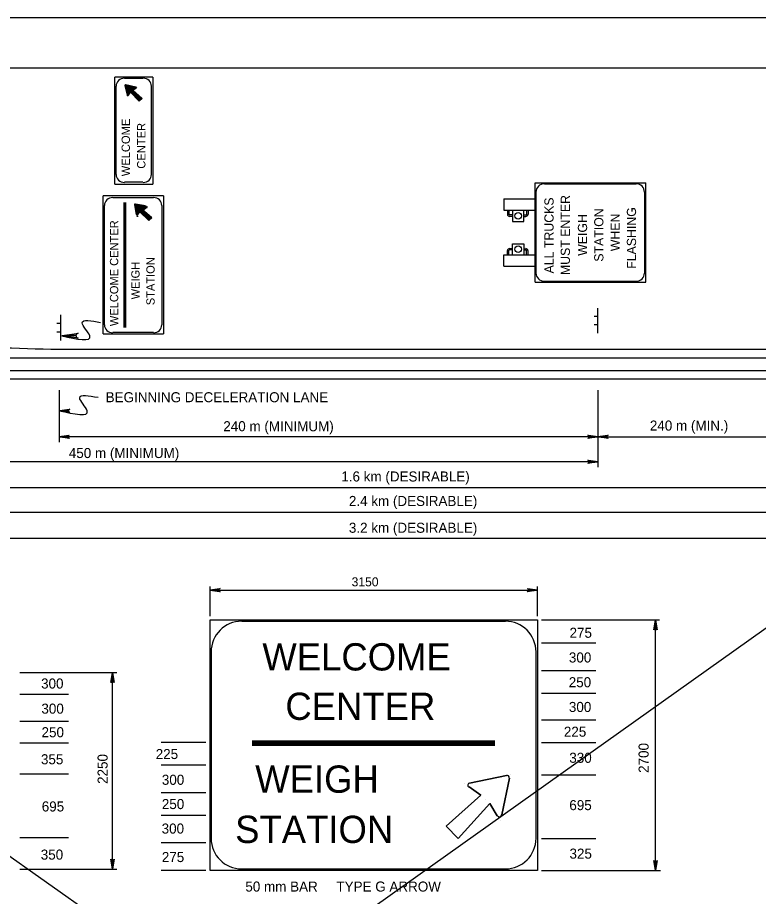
# Model space of a CAD drawing. Extents: x 2189973 to 2192941, y 2147557 to 2151454.
# Drawn here: x 2191146 to 2191872, y 2150594 to 2151454 of the extents above; entities that cross this region are included whole.
import ezdxf

# ---------------------------------------------------------------- set-up
doc = ezdxf.new("R2010")
doc.units = 0
for name, color, linetype in [('1', 7, 'Continuous'), ('Default', 7, 'Continuous'), ('PLT-BNDY', 7, 'Continuous')]:
    doc.layers.add(name, color=color, linetype=linetype)

# ---------------------------------------------------------------- blocks, each defined once
blk = doc.blocks.new('RARROW')
at = {"layer": 'Default'}
blk.add_lwpolyline([(-18.156, 2.28), (-17.479, 0.966), (0, 0), (-18.156, 2.28), (-19.086, 3.077), (0, 0), (-17.465, -0.864), (-18.103, -2.164), (0, 0), (-19.086, -3.033), (-18.103, -2.164)], dxfattribs=at)

msp = doc.modelspace()

# ---------------------------------------------------------------- linework, layer by layer
at = {"layer": '1'}
for p, q in [((2192688.33, 2151431.03), (2190039.06, 2149549.03)), ((2190017.34, 2151423.79), (2192695.57, 2149534.55))]:
    msp.add_line(p, q, dxfattribs=at)
at = {"layer": 'Default'}
for p, q in [((2190104.48, 2151405.2), (2192683.21, 2151405.2)), ((2191241.29, 2151291.19), (2191241.29, 2151396.18)), ((2191278.61, 2151396.18), (2191241.29, 2151396.18)), ((2191250.72, 2151394.94), (2191268.77, 2151394.94)), ((2191278.61, 2151396.18), (2191278.61, 2151291.19)), ((2191242.52, 2151300.62), (2191242.52, 2151387.15)), ((2191251.13, 2151388.38), (2191251.13, 2151388.38)), ((2191251.13, 2151387.56), (2191253.18, 2151378.54)), ((2191261.79, 2151386.33), (2191251.95, 2151388.38)), ((2191257.69, 2151382.23), (2191257.69, 2151382.23)), ((2191258.92, 2151383.46), (2191262.2, 2151385.51)), ((2191258.92, 2151383.46), (2191262.2, 2151385.51)), ((2191258.92, 2151383.46), (2191258.92, 2151383.46)), ((2191267.95, 2151375.26), (2191258.92, 2151383.46)), ((2191263.43, 2151386.33), (2191263.43, 2151386.33)), ((2191276.97, 2151387.15), (2191276.97, 2151300.62)), ((2191253.59, 2151376.9), (2191253.59, 2151376.9)), ((2191254.41, 2151378.13), (2191256.46, 2151381.41)), ((2191256.46, 2151381.41), (2191256.46, 2151381.41)), ((2191256.46, 2151381.41), (2191265.07, 2151372.39)), ((2191265.07, 2151372.39), (2191267.95, 2151375.26)), ((2191267.95, 2151375.26), (2191267.95, 2151375.26)), ((2191265.07, 2151372.39), (2191265.07, 2151372.39)), ((2191241.29, 2151291.19), (2191278.61, 2151291.19)), ((2191268.77, 2151293.24), (2191250.72, 2151293.24)), ((2191653.03, 2151195.22), (2191653.03, 2151292.42)), ((2191653.03, 2151292.42), (2191761.3, 2151292.42)), ((2191662.06, 2151291.6), (2191751.87, 2151291.6)), ((2191761.3, 2151195.22), (2191761.3, 2151292.42)), ((2191229.81, 2151144.78), (2191229.81, 2151279.71)), ((2191288.86, 2151279.71), (2191229.81, 2151279.71)), ((2191288.86, 2151279.71), (2191288.86, 2151144.78)), ((2191653.85, 2151204.25), (2191653.85, 2151283.4)), ((2191760.07, 2151283.4), (2191760.07, 2151204.25)), ((2191231.04, 2151153.39), (2191231.04, 2151270.27)), ((2191239.24, 2151278.07), (2191279.02, 2151278.07)), ((2191250.31, 2151150.93), (2191250.31, 2151273.14)), ((2191250.72, 2151150.93), (2191250.72, 2151273.14)), ((2191251.13, 2151150.93), (2191251.13, 2151273.14)), ((2191251.54, 2151150.93), (2191251.54, 2151273.14)), ((2191251.95, 2151150.93), (2191251.95, 2151273.14)), ((2191260.15, 2151271.91), (2191260.15, 2151271.91)), ((2191260.56, 2151271.09), (2191262.61, 2151261.66)), ((2191271.23, 2151269.86), (2191261.38, 2151271.5)), ((2191287.22, 2151270.27), (2191287.22, 2151153.39)), ((2191622.28, 2151276.83), (2191622.28, 2151265.76)), ((2191622.28, 2151276.83), (2191653.03, 2151276.83)), ((2191263.43, 2151261.25), (2191265.89, 2151264.12)), ((2191265.89, 2151264.12), (2191265.89, 2151264.12)), ((2191265.89, 2151264.12), (2191274.51, 2151255.51)), ((2191266.31, 2151263.3), (2191266.31, 2151263.3)), ((2191266.72, 2151265.35), (2191266.72, 2151265.35)), ((2191267.54, 2151264.53), (2191267.54, 2151264.53)), ((2191267.95, 2151266.58), (2191271.64, 2151268.63)), ((2191267.95, 2151266.58), (2191271.64, 2151268.63)), ((2191267.95, 2151266.58), (2191267.95, 2151266.58)), ((2191277.38, 2151258.38), (2191267.95, 2151266.58)), ((2191268.77, 2151265.76), (2191272.46, 2151268.63)), ((2191268.77, 2151265.76), (2191268.77, 2151265.76)), ((2191272.87, 2151269.45), (2191272.87, 2151269.45)), ((2191622.28, 2151265.76), (2191630.89, 2151265.76)), ((2191625.97, 2151265.76), (2191625.97, 2151261.66)), ((2191627.2, 2151265.76), (2191627.2, 2151261.66)), ((2191630.89, 2151265.76), (2191630.89, 2151254.69)), ((2191630.89, 2151265.76), (2191653.03, 2151265.76)), ((2191641.96, 2151254.69), (2191641.96, 2151265.76)), ((2191644.42, 2151265.76), (2191644.42, 2151261.66)), ((2191646.06, 2151265.76), (2191646.06, 2151261.66)), ((2191263.02, 2151260.02), (2191263.02, 2151260.02)), ((2191274.51, 2151255.51), (2191277.38, 2151258.38)), ((2191274.51, 2151255.51), (2191274.51, 2151255.51)), ((2191277.38, 2151258.38), (2191277.38, 2151258.38)), ((2191630.89, 2151261.25), (2191628.02, 2151261.25)), ((2191630.89, 2151259.61), (2191628.02, 2151259.61)), ((2191630.89, 2151254.69), (2191641.96, 2151254.69)), ((2191641.96, 2151261.25), (2191643.6, 2151261.25)), ((2191641.96, 2151259.61), (2191643.6, 2151259.61)), ((2191630.89, 2151228.03), (2191628.02, 2151228.03)), ((2191630.89, 2151221.88), (2191630.89, 2151232.95)), ((2191630.89, 2151232.95), (2191641.96, 2151232.95)), ((2191641.96, 2151232.95), (2191641.96, 2151221.88)), ((2191641.96, 2151228.03), (2191643.6, 2151228.03)), ((2191622.28, 2151210.81), (2191622.28, 2151221.88)), ((2191622.28, 2151221.88), (2191630.89, 2151221.88)), ((2191625.97, 2151221.88), (2191625.97, 2151226.39)), ((2191627.2, 2151221.88), (2191627.2, 2151226.39)), ((2191630.89, 2151226.8), (2191628.02, 2151226.8)), ((2191630.89, 2151221.88), (2191653.03, 2151221.88)), ((2191641.96, 2151226.8), (2191643.6, 2151226.8)), ((2191644.42, 2151221.88), (2191644.42, 2151226.39)), ((2191646.06, 2151221.88), (2191646.06, 2151226.39)), ((2191622.28, 2151210.81), (2191653.03, 2151210.81)), ((2191653.03, 2151195.22), (2191761.3, 2151195.22)), ((2191751.87, 2151196.04), (2191662.06, 2151196.04)), ((2191714.55, 2151145.19), (2191714.55, 2151169.8)), ((2191188.39, 2151138.22), (2191188.39, 2151163.24)), ((2191714.55, 2151161.6), (2191710.86, 2151161.6)), ((2191188.39, 2151154.62), (2191184.28, 2151154.62)), ((2191714.55, 2151153.39), (2191710.86, 2151153.39)), ((2191188.39, 2151146.42), (2191184.28, 2151146.42)), ((2191229.81, 2151144.78), (2191288.86, 2151144.78)), ((2191279.02, 2151146.01), (2191239.24, 2151146.01)), ((2191186.33, 2151129.61), (2191186.33, 2151129.61)), ((2191186.33, 2151129.61), (2192679.93, 2151129.61)), ((2190114.32, 2151121), (2192679.93, 2151121)), ((2190114.32, 2151108.69), (2192679.93, 2151108.69)), ((2190114.32, 2151100.49), (2192679.93, 2151100.49)), ((2191186.74, 2151089.42), (2191186.74, 2151038.56)), ((2191714.55, 2151089.42), (2191714.55, 2151013.96)), ((2191714.55, 2151043.9), (2191186.74, 2151043.9)), ((2191714.55, 2151043.9), (2191916.68, 2151043.9)), ((2191714.55, 2151019.29), (2190939.04, 2151019.29)), ((2190939.04, 2150994.27), (2192091.43, 2150994.27)), ((2192264.5, 2150969.67), (2190939.04, 2150969.67)), ((2192437.97, 2150944.24), (2190939.04, 2150944.24)), ((2191334.51, 2150868.2), (2191334.51, 2150897.32)), ((2191334.51, 2150893.63), (2191655.21, 2150893.63)), ((2191655.21, 2150868.2), (2191655.21, 2150897.32)), ((2191334.51, 2150864.51), (2191655.21, 2150864.51)), ((2191334.51, 2150618.86), (2191334.51, 2150864.51)), ((2191624.04, 2150862.87), (2191365.68, 2150862.87)), ((2191655.21, 2150864.51), (2191655.21, 2150618.86)), ((2191659.31, 2150864.51), (2191692.12, 2150864.51)), ((2191659.31, 2150864.51), (2191692.12, 2150864.51)), ((2191681.46, 2150864.51), (2191774.97, 2150864.51)), ((2191770.86, 2150618.86), (2191770.86, 2150864.51)), ((2191659.31, 2150841.96), (2191712.43, 2150841.96)), ((2191335.74, 2150832.93), (2191335.74, 2150650.44)), ((2191653.98, 2150650.44), (2191653.98, 2150832.93)), ((2191659.31, 2150814.89), (2191712.43, 2150814.89)), ((2191148.24, 2150812.94), (2191243.22, 2150812.94)), ((2191239.11, 2150620.19), (2191239.11, 2150812.94)), ((2191148.24, 2150791.62), (2191195.99, 2150791.62)), ((2191659.31, 2150792.74), (2191712.43, 2150792.74)), ((2191148.24, 2150765.37), (2191195.99, 2150765.37)), ((2191659.31, 2150766.5), (2191712.43, 2150766.5)), ((2191375.93, 2150745.99), (2191613.38, 2150745.99)), ((2191375.93, 2150745.17), (2191613.38, 2150745.17)), ((2191148.24, 2150744.04), (2191195.99, 2150744.04)), ((2191330.41, 2150744.35), (2191286.76, 2150744.35)), ((2191375.93, 2150744.35), (2191613.38, 2150744.35)), ((2191375.93, 2150743.53), (2191613.38, 2150743.53)), ((2191375.93, 2150742.71), (2191613.38, 2150742.71)), ((2191375.93, 2150741.89), (2191613.38, 2150741.89)), ((2191659.31, 2150744.35), (2191712.43, 2150744.35)), ((2191330.41, 2150722.21), (2191286.76, 2150722.21)), ((2191148.24, 2150713.7), (2191195.99, 2150713.7)), ((2191624.86, 2150711.95), (2191588.77, 2150704.57)), ((2191588.77, 2150704.57), (2191624.86, 2150711.95)), ((2191628.56, 2150712.77), (2191628.56, 2150712.77)), ((2191659.31, 2150712.77), (2191712.43, 2150712.77)), ((2191583.44, 2150703.75), (2191583.44, 2150703.75)), ((2191620.35, 2150673.4), (2191627.73, 2150709.49)), ((2191627.73, 2150709.49), (2191620.35, 2150673.4)), ((2191330.41, 2150695.14), (2191286.76, 2150695.14)), ((2191588.36, 2150700.88), (2191599.85, 2150692.68)), ((2191599.85, 2150692.68), (2191588.36, 2150700.88)), ((2191599.85, 2150692.68), (2191565.81, 2150662.33)), ((2191565.81, 2150662.33), (2191599.85, 2150692.68)), ((2191599.85, 2150692.68), (2191565.81, 2150662.33)), ((2191565.81, 2150662.33), (2191599.85, 2150692.68)), ((2191599.85, 2150692.68), (2191599.85, 2150692.68)), ((2191599.85, 2150692.68), (2191599.85, 2150692.68)), ((2191603.95, 2150688.99), (2191603.95, 2150688.99)), ((2191603.95, 2150688.99), (2191603.95, 2150688.99)), ((2191577.7, 2150650.44), (2191608.46, 2150684.48)), ((2191608.46, 2150684.48), (2191577.7, 2150650.44)), ((2191608.46, 2150684.48), (2191608.46, 2150684.48)), ((2191608.46, 2150684.48), (2191608.46, 2150684.48)), ((2191608.46, 2150684.48), (2191615.84, 2150672.58)), ((2191615.84, 2150672.58), (2191608.46, 2150684.48)), ((2191330.41, 2150672.99), (2191286.76, 2150672.99)), ((2191618.71, 2150668.07), (2191618.71, 2150668.07)), ((2191565.81, 2150662.33), (2191565.81, 2150662.33)), ((2191565.81, 2150662.33), (2191565.81, 2150662.33)), ((2191565.81, 2150662.33), (2191577.7, 2150650.44)), ((2191577.7, 2150650.44), (2191565.81, 2150662.33)), ((2191148.24, 2150651.36), (2191195.99, 2150651.36)), ((2191330.41, 2150645.93), (2191286.76, 2150645.93)), ((2191577.7, 2150650.44), (2191577.7, 2150650.44)), ((2191577.7, 2150650.44), (2191577.7, 2150650.44)), ((2191659.31, 2150650.44), (2191712.43, 2150650.44)), ((2191148.24, 2150620.19), (2191243.22, 2150620.19)), ((2191330.41, 2150618.86), (2191286.76, 2150618.86)), ((2191655.21, 2150618.86), (2191334.51, 2150618.86)), ((2191365.68, 2150620.5), (2191624.04, 2150620.5)), ((2191659.31, 2150618.86), (2191775.88, 2150618.86))]:
    msp.add_line(p, q, dxfattribs=at)
for points in [[(2191267.54, 2151375.26), (2191265.07, 2151372.8), (2191256.46, 2151381.82), (2191254.41, 2151378.54), (2191254, 2151378.54), (2191253.59, 2151378.54), (2191251.54, 2151387.56), (2191251.95, 2151387.97), (2191262.2, 2151385.92), (2191258.51, 2151383.46), (2191267.54, 2151375.26), (2191265.07, 2151373.21), (2191256.46, 2151381.82), (2191254, 2151378.95), (2191254, 2151378.54), (2191251.95, 2151387.56), (2191261.79, 2151385.92), (2191258.51, 2151383.46), (2191267.13, 2151375.26), (2191265.48, 2151373.62), (2191256.46, 2151382.23), (2191254, 2151379.36), (2191252.36, 2151387.15), (2191260.97, 2151385.51), (2191257.69, 2151383.46), (2191266.72, 2151375.26), (2191265.48, 2151374.03), (2191256.46, 2151382.23), (2191254.41, 2151379.77), (2191252.77, 2151386.74), (2191260.15, 2151385.51), (2191257.69, 2151383.46), (2191266.31, 2151375.26), (2191265.48, 2151374.44), (2191256.46, 2151382.64), (2191254.82, 2151380.59), (2191253.59, 2151386.33), (2191259.74, 2151385.1), (2191256.87, 2151383.46), (2191265.89, 2151375.26), (2191265.48, 2151375.26), (2191256.46, 2151383.05), (2191254.82, 2151381.41), (2191254, 2151385.92), (2191258.92, 2151385.1), (2191256.87, 2151383.46), (2191265.89, 2151375.67), (2191265.48, 2151375.26), (2191265.48, 2151374.85), (2191256.46, 2151383.46), (2191265.48, 2151375.67), (2191265.07, 2151375.26), (2191256.46, 2151383.46), (2191255.23, 2151382.23), (2191254.41, 2151385.51), (2191258.1, 2151384.69), (2191255.64, 2151383.05), (2191254.82, 2151385.1), (2191257.69, 2151384.69), (2191256.05, 2151383.46), (2191255.64, 2151385.1), (2191256.87, 2151384.69), (2191256.05, 2151384.28), (2191256.05, 2151384.69), (2191256.46, 2151384.69)], [(2191276.97, 2151258.79), (2191274.51, 2151256.33), (2191265.89, 2151264.53), (2191263.43, 2151261.66), (2191263.02, 2151261.25), (2191262.61, 2151261.66), (2191260.97, 2151271.09), (2191261.38, 2151271.5), (2191271.64, 2151269.04), (2191267.54, 2151266.58), (2191276.97, 2151258.79), (2191274.51, 2151256.74), (2191265.89, 2151264.94), (2191263.43, 2151261.66), (2191263.43, 2151261.66), (2191261.38, 2151271.09), (2191270.82, 2151269.04), (2191267.54, 2151266.17), (2191276.56, 2151258.79), (2191274.51, 2151257.15), (2191265.89, 2151265.35), (2191263.43, 2151262.07), (2191261.79, 2151270.68), (2191270.41, 2151269.04), (2191266.72, 2151266.17), (2191276.15, 2151258.79), (2191274.92, 2151257.56), (2191265.89, 2151265.35), (2191263.84, 2151262.89), (2191262.2, 2151270.27), (2191269.18, 2151268.63), (2191266.72, 2151266.17), (2191275.74, 2151258.79), (2191274.92, 2151257.97), (2191265.89, 2151265.76), (2191264.25, 2151263.71), (2191262.61, 2151269.86), (2191268.36, 2151268.63), (2191266.31, 2151266.17), (2191275.33, 2151258.79), (2191274.92, 2151258.38), (2191265.89, 2151266.17), (2191264.25, 2151264.53), (2191263.43, 2151269.45), (2191267.95, 2151268.63), (2191265.89, 2151266.17), (2191274.92, 2151258.79), (2191274.92, 2151258.38), (2191274.92, 2151258.38), (2191265.89, 2151266.17), (2191274.92, 2151258.79), (2191274.51, 2151258.38), (2191265.89, 2151266.17), (2191264.66, 2151264.94), (2191263.84, 2151269.04), (2191267.13, 2151268.22), (2191265.07, 2151265.76), (2191264.25, 2151268.63), (2191266.72, 2151268.22), (2191265.07, 2151266.58), (2191264.66, 2151268.22), (2191265.89, 2151268.22), (2191265.48, 2151267.4), (2191265.07, 2151268.22), (2191265.89, 2151267.81)], [(2191203.97, 2151141.09), (2191203.56, 2151142.32), (2191189.21, 2151142.73), (2191203.97, 2151141.09), (2191205.2, 2151140.27), (2191189.21, 2151142.73), (2191203.56, 2151143.55), (2191203.97, 2151144.78), (2191189.21, 2151142.73), (2191205.2, 2151145.19), (2191203.97, 2151144.78)]]:
    msp.add_lwpolyline(points, dxfattribs=at)
for centre in [(2191636.41, 2151260.27), (2191636.41, 2151227.49)]:
    msp.add_circle(centre, 3.21, dxfattribs=at)
for centre, radius, start, end in [((2191661.91, 2151283.55), 8.12, 90, 180), ((2191751.98, 2151283.55), 8.12, 0, 90), ((2191627.91, 2151261.64), 2.01, 180, 270), ((2191627.91, 2151261.64), 0.731, 180, 270), ((2191643.89, 2151261.64), 0.731, 270, 0), ((2191643.89, 2151261.64), 2.01, 270, 0), ((2191627.91, 2151226.12), 2.01, 90, 180), ((2191643.89, 2151226.12), 2.01, 0, 90), ((2191627.91, 2151226.12), 0.731, 90, 180), ((2191643.89, 2151226.12), 0.731, 0, 90), ((2191661.91, 2151204.21), 8.12, 180, 270), ((2191751.98, 2151204.21), 8.12, 270, 0), ((2191297.63, 2155830.32), 4702.16, 265.6447, 268.64351), ((2191365.55, 2150833.13), 30, 90, 180), ((2191623.86, 2150833.13), 30, 0, 90), ((2191625.41, 2150709.98), 2.25, 348.26016, 101.73982), ((2191625.41, 2150709.98), 2.25, 348.26016, 101.73982), ((2191589.27, 2150702.47), 2.25, 101.73984, 236.68377), ((2191589.27, 2150702.47), 2.25, 101.73984, 236.68377), ((2191617.9, 2150673.84), 2.25, 213.31623, 348.26016), ((2191617.9, 2150673.84), 2.25, 213.31623, 348.26016), ((2191365.55, 2150650.53), 30, 180, 270), ((2191623.86, 2150650.53), 30, 270, 0)]:
    msp.add_arc(centre, radius, start, end, dxfattribs=at)
for centre, major_axis, start_param, end_param in [((2191250.71, 2151387.26), (-8.16, 0), 4.712389, 6.283185), ((2191269.02, 2151387.26), (8.16, 0), 0, 1.570796), ((2191251.81, 2151387.91), (-0.619, 0), 4.50749, 6.488084), ((2191261.75, 2151385.95), (0.619, 0), 5.293867, 7.649083), ((2191253.87, 2151378.47), (0.619, 0), 3.346491, 5.701707), ((2191250.71, 2151300.64), (-8.16, 0), 0, 1.570796), ((2191269.02, 2151300.64), (8.16, 0), 4.712389, 6.283185), ((2191239.23, 2151270.39), (-8.12, 0), 4.712389, 6.283185), ((2191261.07, 2151271.04), (-0.619, 0), 4.50749, 6.488084), ((2191261.15, 2151270.96), (-0.688, 0), 4.50749, 6.488084), ((2191279.18, 2151270.39), (8.12, 0), 0, 1.570796), ((2191271.01, 2151269.07), (0.619, 0), 5.293867, 7.649083), ((2191272.19, 2151268.78), (0.688, 0), 5.293867, 7.649083), ((2191263.14, 2151261.59), (0.619, 0), 3.346491, 5.701707), ((2191263.44, 2151260.47), (0.688, 0), 3.346491, 5.701707), ((2191239.23, 2151153.46), (-8.12, 0), 0, 1.570796), ((2191279.18, 2151153.46), (8.12, 0), 4.712389, 6.283185)]:
    msp.add_ellipse(centre, major_axis=major_axis, ratio=0.95, start_param=start_param, end_param=end_param, dxfattribs=at)
for points in [[(2191189.21, 2151142.73), (2191216.68, 2151142.73), (2191209.3, 2151155.44), (2191227.35, 2151155.85)], [(2191186.74, 2151069.32), (2191214.22, 2151069.32), (2191206.84, 2151082.04), (2191224.88, 2151082.45)]]:
    msp.add_spline(points, degree=3, dxfattribs=at)
at = {"layer": 'PLT-BNDY'}
msp.add_lwpolyline([(2189973.25, 2151454.41), (2192732.43, 2151454.41), (2192732.43, 2149505.6), (2189973.25, 2149505.6)], close=True, dxfattribs=at)

# ---------------------------------------------------------------- block references
at = {"layer": 'Default', "xscale": 0.515679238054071, "yscale": 0.5369477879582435}
for p, rotation in [((2191187.3, 2151069.32), 180), ((2191186.74, 2151043.9), 180), ((2191714.55, 2151043.9), 180), ((2191334.51, 2150893.63), 180), ((2191770.86, 2150864.51), 89.99999999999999), ((2191239.11, 2150812.94), 89.99999999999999), ((2191239.11, 2150620.19), -90.00000000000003), ((2191770.86, 2150618.86), -90.00000000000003)]:
    msp.add_blockref('RARROW', p, dxfattribs=dict(at, rotation=rotation))
for p in [(2191714.55, 2151043.9), (2191714.55, 2151019.29), (2191655.21, 2150893.63)]:
    msp.add_blockref('RARROW', p, dxfattribs=at)

# ---------------------------------------------------------------- texts
at = {"layer": 'Default'}
for s, height, rotation, p in [('WELCOME', 8.162, 90, (2191256.05, 2151298.98)), ('CENTER', 8.162, 90, (2191271.23, 2151306.36)), ('MUST ENTER', 9.018, 90, (2191687.07, 2151202.2)), ('ALL TRUCKS', 9.018, 90, (2191671.08, 2151203.84)), ('STATION', 9.018, 90, (2191719.88, 2151215.32)), ('FLASHING', 9.018, 90, (2191751.87, 2151208.35)), ('WELCOME CENTER', 8.1127, 90, (2191244.57, 2151152.16)), ('WEIGH', 9.018, 90, (2191703.89, 2151221.06)), ('WHEN', 9.018, 90, (2191735.87, 2151225.57)), ('STATION', 8.113, 90, (2191280.25, 2151172.67)), ('WEIGH', 8.113, 90, (2191265.48, 2151178.41)), ('WELCOME', 26.717, 360, (2191385.77, 2150814.89)), ('CENTER', 26.717, 360, (2191408.33, 2150766.5)), (' 2700', 9.842, 90, (2191764.16, 2150710.94)), ('2250', 9.842, 90, (2191234.18, 2150703.78)), ('WEIGH', 26.717, 360, (2191378.8, 2150695.14)), ('STATION', 26.717, 360, (2191359.12, 2150645.93))]:
    msp.add_text(s, height=height, rotation=rotation, dxfattribs=at).set_placement(p)
for s, height, p in [('BEGINNING DECELERATION LANE', 9.8425, (2191232.27, 2151077.63)), ('240 m (MINIMUM)', 9.8425, (2191347.51, 2151049.23)), ('240 m (MIN.)', 9.8425, (2191765.38, 2151049.88)), ('450 m (MINIMUM)', 9.8425, (2191196.18, 2151022.98)), (' 1.6 km (DESIRABLE)', 9.8425, (2191459.46, 2151000.01)), ('2.4 km (DESIRABLE)', 9.8425, (2191470.54, 2150976.02)), ('3.2 km (DESIRABLE)', 9.8425, (2191470.54, 2150949.78)), ('3150', 8.858, (2191473.24, 2150897.3)), ('275', 9.842, (2191686.7, 2150846.91)), ('300', 9.842, (2191686.06, 2150822.72)), ('300', 9.842, (2191169.03, 2150797.21)), ('250', 9.842, (2191685.91, 2150798.48)), ('300', 9.842, (2191169.32, 2150772.61)), ('300', 9.842, (2191686.06, 2150774.25)), ('250', 9.842, (2191169.46, 2150749.52)), (' 225', 9.842, (2191677.48, 2150750.02)), (' 225', 9.842, (2191277.65, 2150728.15)), ('355', 9.842, (2191168.89, 2150723.02)), ('330', 9.842, (2191686.45, 2150724.48)), ('300', 9.842, (2191287.32, 2150702.93)), ('695', 9.842, (2191169.69, 2150676.8)), ('250', 9.842, (2191287.32, 2150679.15)), ('695', 9.842, (2191686.49, 2150678.1)), ('300', 9.842, (2191287.12, 2150655.16)), ('350', 9.842, (2191168.69, 2150629.64)), ('275', 9.842, (2191287.3, 2150627.26)), ('325', 9.842, (2191686.66, 2150630.61)), ('50 mm BAR     TYPE G ARROW', 9.8425, (2191369.11, 2150598.35))]:
    msp.add_text(s, height=height, dxfattribs=at).set_placement(p)

doc.saveas('drawing.dxf')
